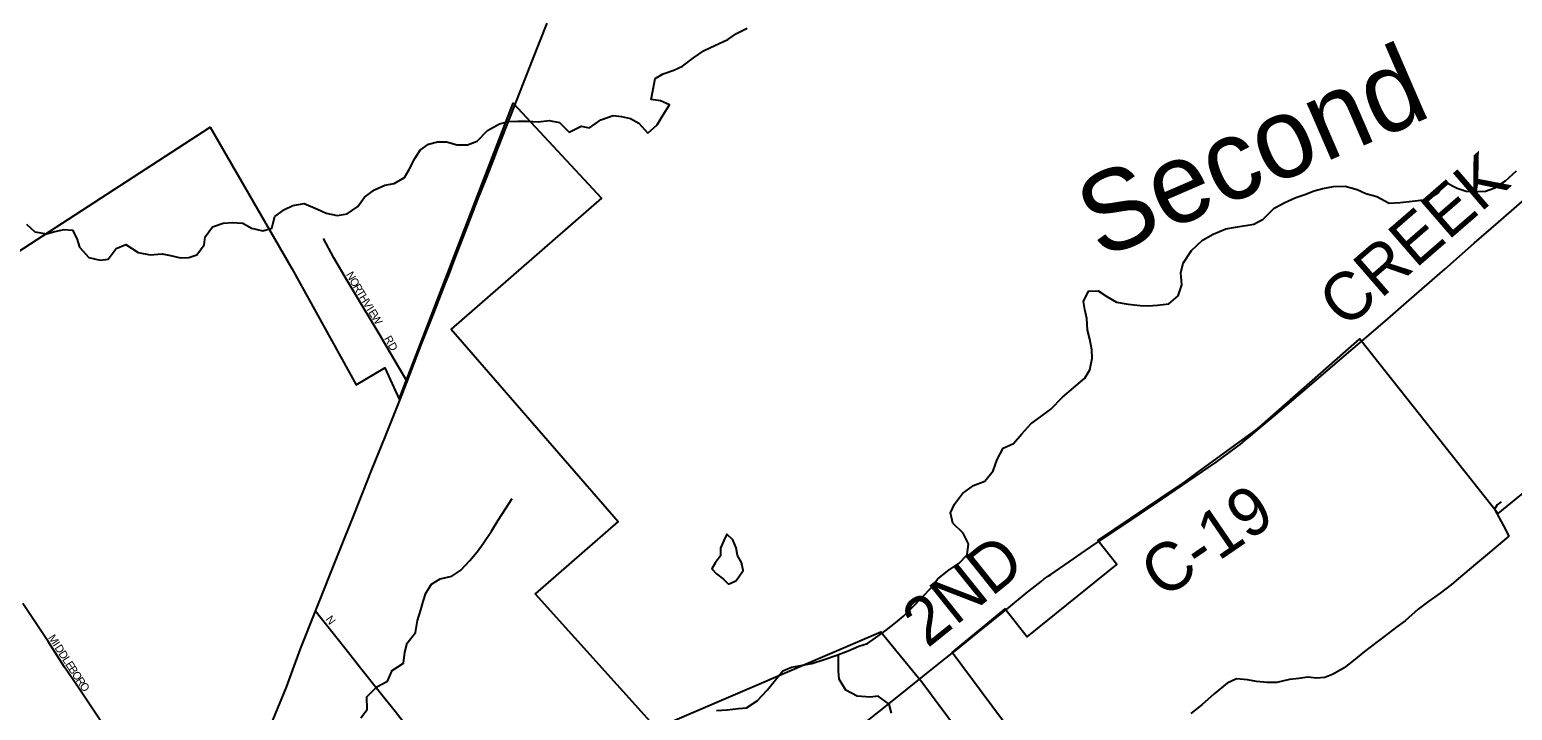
# Model space of a CAD drawing. Extents: x 1442749 to 1756758, y 235267 to 677782.
# Drawn here: x 1545014 to 1554277, y 477359 to 481611 of the extents above; entities that cross this region are included whole.
import ezdxf

# ---------------------------------------------------------------- set-up
doc = ezdxf.new("R2010")
doc.units = 0
for name, color, linetype in [('GM_X_City_Street', 7, 'Continuous'), ('GM_X_City_Street_Text', 7, 'Continuous'), ('GM_X_Corporation', 7, 'Continuous'), ('GM_X_County_Road', 7, 'Continuous'), ('GM_X_County_Road_Text', 7, 'Continuous'), ('GM_X_Minor_Lake', 7, 'Continuous'), ('GM_X_Minor_River', 7, 'Continuous'), ('GM_X_Minor_River_Text', 7, 'Continuous'), ('GM_X_State_Route', 7, 'Continuous'), ('GM_X_Township_Subdivision', 7, 'Continuous'), ('GM_X_Township_Subdivision_Text', 7, 'Continuous')]:
    doc.layers.add(name, color=color, linetype=linetype)

msp = doc.modelspace()

# ---------------------------------------------------------------- linework, layer by layer
at = {"layer": 'GM_X_City_Street'}
for points in [[(1545586.4, 477095.2), (1545500.1, 477228.8), (1545412.7, 477359.8), (1545312.6, 477509.9), (1545232.1, 477630), (1545128.4, 477789.5), (1544970.3, 478027.3)], [(1547385.8, 477239.2), (1547363.9, 477266.3), (1547297.3, 477351.6), (1547204, 477469.8), (1547080.8, 477623.3), (1546999.6, 477726.1), (1546853, 477911.2), (1546820.3, 477952.3), (1546799.5, 477978.3)], [(1549663.6, 476821.3), (1549753.5, 476893.2), (1550081.3, 477160.4), (1550219, 477271.7), (1550401.1, 477416.6), (1550593.9, 477571.2)]]:
    msp.add_lwpolyline(points, dxfattribs=at)
at = {"layer": 'GM_X_Corporation'}
for points in [[(1544815.7, 480142.1), (1546141.6, 481003.1), (1546652.1, 480118.9), (1547054.5, 479393), (1547232, 479499.6), (1547321.8, 479303.4), (1548033.8, 481151.3), (1548587, 480558.1), (1547646, 479739.9), (1548690.6, 478538.3), (1548172, 478087.4), (1548928.2, 477247.6), (1550330.3, 477849.1), (1550566.2, 477562.9), (1550587.4, 477537.2), (1551508.7, 476298.7)], [(1551647.8, 476550.7), (1550776.2, 477720.2), (1551107.5, 477993.5), (1551244.9, 477819.4), (1551804.9, 478271), (1551687.6, 478419.7), (1552184.9, 478755.1), (1552219.3, 478778.3), (1552309.7, 478844.2), (1552685.2, 479117.8), (1552716.5, 479145.3), (1553324.4, 479679.3), (1554187.6, 478589.1), (1555499.2, 479656.8)]]:
    msp.add_lwpolyline(points, dxfattribs=at)
at = {"layer": 'GM_X_County_Road'}
for points in [[(1553322.8, 479654.9), (1553408.2, 479728.3), (1553497.9, 479805.2), (1553631.1, 479921.9), (1553853.8, 480115.4), (1554038.9, 480277.6), (1554190.7, 480408.1), (1554420, 480609.2), (1554509.7, 480690.9), (1554599.2, 480773.3)], [(1551507.5, 478287.5), (1551637.9, 478375.7), (1551945.5, 478582.6), (1552051.8, 478653.8), (1552295.7, 478820), (1552425.2, 478909.5), (1552465, 478938.1), (1552504.9, 478967), (1552539.7, 478993.3), (1552575.2, 479020.6), (1552610.1, 479049), (1552638.8, 479072.2), (1552669.3, 479098.1), (1552781.4, 479193), (1553038.6, 479412.1), (1553226.1, 479571.3), (1553322.8, 479654.9)], [(1550926.3, 477838.1), (1551128, 478000.1), (1551240.1, 478090.6), (1551295.6, 478135.4), (1551314.4, 478150.5), (1551332, 478164.8), (1551352.5, 478179.9), (1551376.9, 478197.9), (1551392.9, 478209), (1551507.5, 478287.5)], [(1550593.9, 477571.2), (1550739.8, 477687.5), (1550821.9, 477753), (1550926.3, 477838.1)]]:
    msp.add_lwpolyline(points, dxfattribs=at)
at = {"layer": 'GM_X_Minor_Lake'}
for points in [[(1549439.5, 478186.7), (1549470.2, 478232.4), (1549460.9, 478282.6), (1549435.5, 478327.1), (1549428.2, 478375.3), (1549406.8, 478423.7), (1549369.3, 478460.3), (1549350.7, 478420.4), (1549330, 478372.6), (1549329.3, 478324.5), (1549317.8, 478308.8)], [(1549317.8, 478308.8), (1549298.7, 478282.8), (1549276.1, 478243), (1549303.7, 478212.6), (1549349.3, 478177.9), (1549378.9, 478147.4), (1549425.2, 478168.8), (1549439.5, 478186.7)]]:
    msp.add_lwpolyline(points, dxfattribs=at)
at = {"layer": 'GM_X_Minor_River'}
for points in [[(1548874.7, 480964.8), (1548933.5, 481016.2), (1548970.4, 481079.8), (1549011.3, 481141.4), (1548955.6, 481166.2), (1548895.7, 481175.1), (1548908.6, 481239), (1548921.6, 481307), (1548972.1, 481334.4), (1549038.5, 481357.5), (1549092.9, 481382.9), (1549161.7, 481436), (1549228.4, 481481.2), (1549294.9, 481512.4), (1549375.5, 481549.4), (1549430.1, 481586.8), (1549496.7, 481619.9)], [(1544994.7, 480396.2), (1545046, 480347.4), (1545119.9, 480336.4), (1545170.2, 480349.7), (1545228.4, 480363), (1545280.4, 480358.2), (1545307.7, 480305.8), (1545325, 480253.4), (1545384.1, 480188.5), (1545453.9, 480171.5), (1545504, 480176.8), (1545553.1, 480244.3), (1545615.5, 480269.5), (1545690.8, 480218.4), (1545766.7, 480205.3), (1545840.9, 480210.3), (1545892.8, 480199.6), (1545956.6, 480186.7), (1546008.7, 480188), (1546059, 480205.3), (1546103.9, 480266.8), (1546110.7, 480316.9), (1546155.6, 480380.4), (1546222, 480401.6), (1546278.1, 480406.8), (1546346.1, 480401.9), (1546399.7, 480371.1), (1546469.5, 480354.1), (1546525.8, 480371.4), (1546544.9, 480443.3), (1546605.6, 480488.6), (1546658, 480511.9), (1546728.2, 480525), (1546811.8, 480489.8), (1546865.5, 480465), (1546935.4, 480450), (1546997.6, 480461.2), (1547064.3, 480506.4), (1547105.2, 480563.9), (1547167.9, 480611.2), (1547232.4, 480640.4), (1547290.6, 480649.6), (1547355.2, 480686.8), (1547383.9, 480738.6), (1547419, 480806.2), (1547453.7, 480857.9), (1547506.3, 480895.3), (1547562.6, 480910.5), (1547618.6, 480909.8), (1547684.4, 480890.8), (1547748.5, 480892), (1547808.9, 480915.2), (1547873.9, 480980.5), (1547948.6, 481023.6), (1548006.8, 481036.8), (1548062.9, 481040), (1548123, 481039.2), (1548191, 481036.3), (1548259.2, 481043.4), (1548323.1, 481030.5), (1548384.3, 480971.5), (1548458.9, 481008.6), (1548510.8, 480997.9), (1548581.6, 481047), (1548658.1, 481076), (1548712, 481069.3), (1548767.9, 481056.5), (1548819.5, 481027.7), (1548874.7, 480964.8)], [(1550645.8, 478124.2), (1550684.6, 478179.8), (1550749.4, 478231), (1550820.2, 478278.1), (1550871, 478331.6), (1550878, 478399.7), (1550844.9, 478466.3), (1550781.7, 478529.3), (1550766.6, 478593.6), (1550791.4, 478647.4), (1550842.4, 478714.9), (1550909.2, 478764.1), (1550981.7, 478791.2), (1551032.6, 478854.6), (1551057.7, 478926.5), (1551094.7, 478996.1), (1551159.2, 479027.3), (1551212.1, 479086.7), (1551269.1, 479150.1), (1551327.8, 479193.4), (1551392.5, 479240.6), (1551465.7, 479315.8), (1551534.6, 479373), (1551605.5, 479434.2), (1551636.3, 479485.9), (1551651.4, 479559.9), (1551650.1, 479612), (1551637, 479678.3), (1551621.8, 479734.7), (1551618.9, 479806.9), (1551605.7, 479863.2), (1551596.4, 479913.5), (1551629.3, 479977.2), (1551689.4, 479980.3), (1551742.9, 479943.5), (1551804.5, 479908.6), (1551876.4, 479897.6), (1551950.4, 479888.6), (1552002.4, 479885.9), (1552060.5, 479891.1), (1552130.7, 479898.2), (1552189.5, 479949.5), (1552212.5, 480017.3), (1552205.5, 480091.6), (1552220.4, 480153.5), (1552271.6, 480231), (1552340.6, 480296.2), (1552407.2, 480333.4), (1552485.7, 480366.5), (1552546, 480377.7), (1552662.3, 480396.1), (1552718.8, 480427.4), (1552787.9, 480496.6), (1552854.5, 480531.8), (1552923, 480563), (1552979.3, 480582.2), (1553037.7, 480605.5), (1553092, 480618.8), (1553160.2, 480631.9), (1553232.3, 480632.9), (1553306.1, 480611.9), (1553361.8, 480587.1), (1553429.6, 480570.1), (1553507.1, 480527), (1553575.2, 480532.1), (1553631.3, 480537.3), (1553687.5, 480544.6), (1553747.6, 480551.8), (1553812.3, 480593), (1553859.3, 480658.5), (1553932.8, 480621.4), (1553988.6, 480602.6), (1554038.6, 480599.9), (1554108.7, 480603), (1554167.1, 480624.2), (1554233.8, 480667.5), (1554302.7, 480728.6)], [(1547082.6, 477312.6), (1547121.3, 477364.2), (1547120.5, 477444.4), (1547183.4, 477505.7), (1547250, 477540.9), (1547279, 477608.7), (1547349.7, 477653.8), (1547356.7, 477723.9), (1547371.6, 477779.8), (1547424.6, 477845.2), (1547437.7, 477921.2), (1547456.6, 477987.1), (1547471.4, 478039), (1547488.2, 478091), (1547525, 478146.6), (1547577.5, 478179.9), (1547651.8, 478197), (1547708.4, 478234.3), (1547763.4, 478295.7), (1547810.2, 478349.2), (1547847, 478400.8), (1547898.1, 478478.3), (1547941.2, 478547.9), (1547986.2, 478617.4), (1548027.2, 478683)], [(1554207.7, 478661.6), (1554182.7, 478643.4), (1554164.5, 478615.9), (1554220.9, 478512.6), (1554254, 478448), (1554187.1, 478390.8), (1554134.4, 478345.4), (1554059.4, 478282.2), (1553966.2, 478205.3), (1553897.3, 478146.1), (1553826.4, 478091), (1553755.7, 478041.8), (1553688.8, 477990.6), (1553607.8, 477919.5), (1553555.2, 477882.1), (1553500.5, 477838.8), (1553431.7, 477787.6), (1553352.7, 477726.5), (1553283.9, 477671.3), (1553225.2, 477626), (1553156.5, 477584.8), (1553104.2, 477565.5), (1553054, 477560.2), (1552998.1, 477566.9), (1552941.9, 477557.7), (1552883.8, 477552.5), (1552805.4, 477533.5), (1552745.4, 477534.3), (1552677.4, 477539.2), (1552621.5, 477550), (1552553.5, 477557), (1552495.1, 477529.7), (1552414, 477462.6), (1552336.9, 477393.5), (1552268.1, 477340.3)], [(1549305.4, 477358.5), (1549371.5, 477361.7), (1549441.7, 477370.7), (1549491.9, 477376.1), (1549558.6, 477419.3), (1549623.6, 477488.5), (1549664.4, 477540.1), (1549719.4, 477605.5), (1549773.8, 477628.8), (1549842, 477641.9), (1549900.2, 477651.2), (1549976.7, 477676.2), (1550051.1, 477701.2), (1550127.6, 477730.3), (1550194.1, 477759.4), (1550248.4, 477776.7), (1550298.9, 477812.1), (1550363.7, 477859.4), (1550422.4, 477906.7), (1550473.1, 477948.1), (1550532, 478005.4), (1550588.9, 478066.8), (1550645.8, 478124.2)], [(1550065.8, 477606.8), (1550065.9, 477706.8)], [(1550398.3, 477341.7), (1550383.1, 477398), (1550313.7, 477447.1), (1550263.6, 477441.8), (1550183.6, 477448.8), (1550112.1, 477485.9), (1550071, 477554.6), (1550065.8, 477606.8)]]:
    msp.add_lwpolyline(points, dxfattribs=at)
at = {"layer": 'GM_X_State_Route'}
for points in [[(1548018.9, 481075.4), (1548155.9, 481421.3), (1548247, 481651.1)], [(1546440.7, 477076.5), (1546487, 477189.6), (1546534.4, 477301.4), (1546617.6, 477504.8), (1546706.7, 477743.8), (1546799.5, 477978.3), (1546942.3, 478338.7), (1547040.1, 478582.4), (1547149.4, 478856.6), (1547236.1, 479072.8), (1547327.5, 479301.2), (1547371.3, 479414.4), (1547459.2, 479641.6), (1547537.8, 479839.7), (1547604.5, 480013.8), (1547633.5, 480084.9), (1547670.2, 480179.1), (1547773.2, 480448.6), (1547811.7, 480546.2), (1547864.9, 480680.2), (1547913.2, 480802.1), (1547942.8, 480878.6), (1548018.9, 481075.4)]]:
    msp.add_lwpolyline(points, dxfattribs=at)
at = {"layer": 'GM_X_Township_Subdivision'}
for points in [[(1547000.1, 480041), (1546914.8, 480186.6), (1546849, 480306.4)], [(1547196.4, 479710.6), (1547043, 479968.1), (1547000.1, 480041)], [(1547371.3, 479414.4), (1547296.9, 479540.7), (1547267.4, 479591.3), (1547196.4, 479710.6)]]:
    msp.add_lwpolyline(points, dxfattribs=at)

# ---------------------------------------------------------------- texts
at = {"layer": 'GM_X_City_Street_Text'}
for s, rotation, p in [('N', 306.87427, (1546860, 477927.7)), ('M', 302.91469, (1545126.8, 477812.8)), ('I', 302.91718, (1545155.4, 477768.4)), ('D', 302.91119, (1545167.4, 477750)), ('D', 302.91642, (1545191.3, 477713)), ('L', 302.91971, (1545215.2, 477676.1)), ('E', 302.90592, (1545234.4, 477646.6)), ('B', 302.91241, (1545253.5, 477617)), ('O', 302.90573, (1545275, 477583.8)), ('R', 303.44978, (1545299.2, 477546.4)), ('O', 305.57564, (1545322.2, 477511.7))]:
    msp.add_text(s, height=50, rotation=rotation, dxfattribs=at).set_placement(p)
at = {"layer": 'GM_X_County_Road_Text'}
for s, rotation, p in [('CREEK', 40.90385, (1553234.6, 479736.3)), ('C-19', 34.35041, (1552091.6, 478050.2)), ('2ND', 38.76919, (1550622.4, 477744.3))]:
    msp.add_text(s, height=300, rotation=rotation, dxfattribs=at).set_placement(p)
at = {"layer": 'GM_X_Minor_River_Text'}
msp.add_text('Second', height=499.97, rotation=23.40714, dxfattribs=at).set_placement((1551703.4, 480175.1))
at = {"layer": 'GM_X_Township_Subdivision_Text'}
for s, rotation, p in [('N', 299.27324, (1546988.2, 480082.7)), ('O', 299.27315, (1547009.8, 480044.3)), ('R', 299.68259, (1547031.5, 480005.6)), ('T', 301.10004, (1547051.8, 479970)), ('H', 301.45529, (1547070.1, 479939.6)), ('V', 301.47087, (1547093.1, 479902)), ('I', 301.49328, (1547116.1, 479864.5)), ('E', 301.46972, (1547127.6, 479845.7)), ('W', 301.48404, (1547145.9, 479815.7)), ('RD', 299.36165, (1547225.8, 479682.3))]:
    msp.add_text(s, height=50, rotation=rotation, dxfattribs=at).set_placement(p)

doc.saveas('drawing.dxf')
